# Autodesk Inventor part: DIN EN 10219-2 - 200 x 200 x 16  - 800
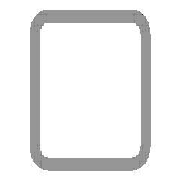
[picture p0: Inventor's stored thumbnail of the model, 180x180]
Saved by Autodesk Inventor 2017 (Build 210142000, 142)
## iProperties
Created: 2017-11
Part Number: DIN EN 10219-2 - 200 x 200 x 16  - 800
Material: Steel, Mild
Description: Cold formed welded structural hollow sections of non-alloy and fine grain structural steel
Document SubType Name: Modeling
Standard: DIN
Designer: iusti
Standard Revision: 2006-07
Standards Organization: DIN
Language: en-US
Size Designation: 200 x 200 x 16
Categories: <MemberInstance><Categories><Category DisplayName="Structural Shapes" InternalName="089c4875-fa83-4c05-b084-43b9cc11f5ed" Mnemonic="GRDR"><CategoryParameter Dis
Stock Number: 200 x 200 x 16
Mass: 67053.1 g
Surface Area: 10890.8 cm^2
Volume: 8541.79 cm^3
Density: 7.85 g/cm^3
Appearance: Semi-Polished
IsCustomPart: 1
_CCFamilyMember: 103
_CCFamilyDisplayName: DIN EN 10219-2 (Square Hollow Section - Cold Formed) - Cold formed welded structural hollow sections of non-alloy and fine grain structural steel
_FrameMemberDoc: Frame Member File
_Version: 15.0.0
_GetPNFromCC: 1
Author: iusti
G_L: 800.000 mm
G_W: 200.000 mm
G_H: 200.000 mm
+7D1ACB6B-707D-4FA8-9414-CBA81EBC054A+CUTDETAIL1: Cut
+A291D230-5091-4B43-A225-1E0F01C6EB95+CUTDETAIL2: Cut
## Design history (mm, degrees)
node "Start plane"
node "End plane"
sketch "Sketch"
  geometry: L1 (-100, -52)-(-100, 52); L2 (-52, 100)-(52, 100); L3 (100, 52)-(100, -52); L4 (52, -100)-(-52, -100); L5 (-52, 84)-(52, 84); L6 (84, 52)-(84, -52); L7 (52, -84)-(-52, -84); L8 (-84, -52)-(-84, 52); L9 (0, 153.918)-(0, -153.918) reference; L10 (-153.918, 0)-(153.918, 0) reference; A1 r 48 centre (-52, -52) between (-100, -52) and (-52, -100); A2 r 48 centre (-52, 52) between (-52, 100) and (-100, 52); A3 r 48 centre (52, 52) between (100, 52) and (52, 100); A4 r 48 centre (52, -52) between (52, -100) and (100, -52); A5 r 32 centre (-52, 52) between (-52, 84) and (-84, 52); A6 r 32 centre (52, 52) between (84, 52) and (52, 84); A7 r 32 centre (52, -52) between (52, -84) and (84, -52); A8 r 32 centre (-52, -52) between (-84, -52) and (-52, -84)
  constraints: 16 end point, 16 point on circle, 8 centre point, 8 tangent, 4 parallel, 3 equal radius, 2 perpendicular, 7 other
  dimensions: "d7" = 48 radius of A1 (= G_IR); "d10" = 200 distance between parallel lines of L2 L4 (= G_H); "d11" = 200 distance between parallel lines of L1 L3 (= G_W); "d12" = 16 distance between parallel lines of L3 L6 (= G_T); "d15" = 100 distance between parallel lines of L2 L10 (= 0.5 x d10); "d16" = 100 distance between parallel lines of L9 L3 (= 0.5 x d11)
extrude "Body" new body sketch "Sketch" stored distance "d3" = 800 (= G_L); taper "d4" = 0 deg
node "Driven Length"
  sketch "Sketch3"
    geometry: L1 (0, 0)-(10, 0) reference
    constraints: 2 end point, 1 horizontal
  workplane "Work Plane3"
  sketch "Sketch4"
    geometry: L1 (-2, 100)-(12, 100) reference; L2 (-2, 900)-(12, 900) reference
    dimensions: "d18" = 800 distance between parallel lines of L1 L2 (derived)
workplane "Work Plane4"
split "Split1"
workplane "Work Plane5"
split "Split2"
body "Solid1"
other parameters: "G_W" = 200 [user parameter; used in 1 equation term], "G_H" = 200 [user parameter; used in 1 equation term], "G_T" = 16 [user parameter; used in 1 equation term], "G_IR" = 48 [user parameter; used in 1 equation term], "G_L" = 800 (= d18) [user parameter; used in 1 equation term], "d17" = 90 deg
